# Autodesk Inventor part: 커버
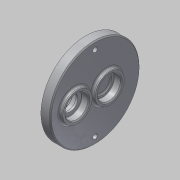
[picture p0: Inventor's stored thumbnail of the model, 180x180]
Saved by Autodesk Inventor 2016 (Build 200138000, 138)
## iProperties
Created: 2016-02
Part Number: 커버
Material: 알루미늄 6061
Document SubType Name: Modeling
Designer: mduedu
Density: 2.71 g/cm^3
Appearance: 알루미늄 - 평지
Author: mduedu
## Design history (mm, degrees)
sketch "스케치1"
  geometry: C1 r 43 at (0, 0); 1 further point
  constraints: 1 centre point, 1 coincident
  dimensions: "d0" = 86 diameter of C1
extrude "돌출1" new body sketch "스케치1" distance "d1" = 9; taper "d2" = 0 deg
sketch "스케치2"
  geometry: C1 r 14 at (0, 11); 1 further point
  constraints: 1 centre point, 1 vertical alignment
  dimensions: "d3" = 28 diameter of C1; "d6" = 11 distance of C1.centre point (0, 0)
extrude "돌출2" join sketch "스케치2" distance "d7" = 3; taper "d8" = 0 deg
sketch "스케치3"
  geometry: C1 r 14 at (0, -20); 1 further point
  constraints: 1 centre point, 1 vertical alignment
  dimensions: "d9" = 28 diameter of C1; "d10" = 20 distance of C1.centre point (0, 0)
extrude "돌출3" join sketch "스케치3" distance "d11" = 3; taper "d12" = 0 deg
hole "구멍1" diameter "d15" = 22; stored, may be unused: countersink angle "d19" = 90 deg, drill point angle "d21" = 0 deg; dims "d13" = 10, "d14" = 10, "d16" = 6, "d17" = 4, "d18" = 2, "d20" = 7
hole "구멍2" diameter "d24" = 18; stored, may be unused: countersink angle "d28" = 90 deg, drill point angle "d30" = 0 deg; dims "d22" = 10, "d23" = 10, "d25" = 6, "d26" = 4, "d27" = 2, "d29" = 1
hole "구멍3" diameter "d33" = 22; stored, may be unused: countersink angle "d37" = 90 deg, drill point angle "d39" = 0 deg; dims "d34" = 6, "d35" = 4, "d36" = 2, "d38" = 7, "d73" = 10, "d74" = 10
sketch "스케치4"
  geometry: C1 r 14 at (0, -20) reference; C2 r 18 at (0, -20); 1 further point
  constraints: 1 centre point, 1 coincident
  dimensions: "d40" = 36 diameter of C2
extrude "돌출4" join sketch "스케치4" distance "d41" = 4; taper "d42" = 0 deg
hole "구멍4" diameter "d45" = 22; stored, may be unused: countersink angle "d49" = 90 deg, drill point angle "d51" = 0 deg; dims "d43" = 10, "d44" = 10, "d46" = 6, "d47" = 4, "d48" = 2, "d50" = 7
hole "구멍5" diameter "d54" = 15; stored, may be unused: countersink angle "d58" = 90 deg, drill point angle "d60" = 0 deg; dims "d52" = 10, "d53" = 10, "d55" = 6, "d56" = 4, "d57" = 2, "d59" = 7
fillet "모깎기1" dims "d61" = 0.3
fillet "모깎기2" dims "d62" = 2
chamfer "모따기1" distance "d63" = 1; stored, may be unused: second distance "d64" = 2, angle "d65" = 45 deg
fillet "모깎기6" dims "d88" = 2
sketch "스케치5" dims "d67" = 72
  geometry: 4 further points
  constraints: 2 horizontal alignment, 1 coincident, 5 other
  dimensions: "d71" = 360 deg dimension on point (0, 0) point (-36, 0) (derived)
fillet "모깎기4" dims "d75" = 2
sketch "스케치6"
  geometry: 2 further points
hole "구멍6" sketch "스케치6" at (36, 0), (-36, 0) diameter "d76" = 4.5; stored, may be unused: countersink angle "d80" = 90 deg, drill point angle "d82" = 0 deg; dims "d77" = 6, "d78" = 8, "d79" = 4.6, "d81" = 8
chamfer "모따기2" distance "d90" = 1; stored, may be unused: second distance "d91" = 2, angle "d92" = 45 deg
node "솔리드1"
